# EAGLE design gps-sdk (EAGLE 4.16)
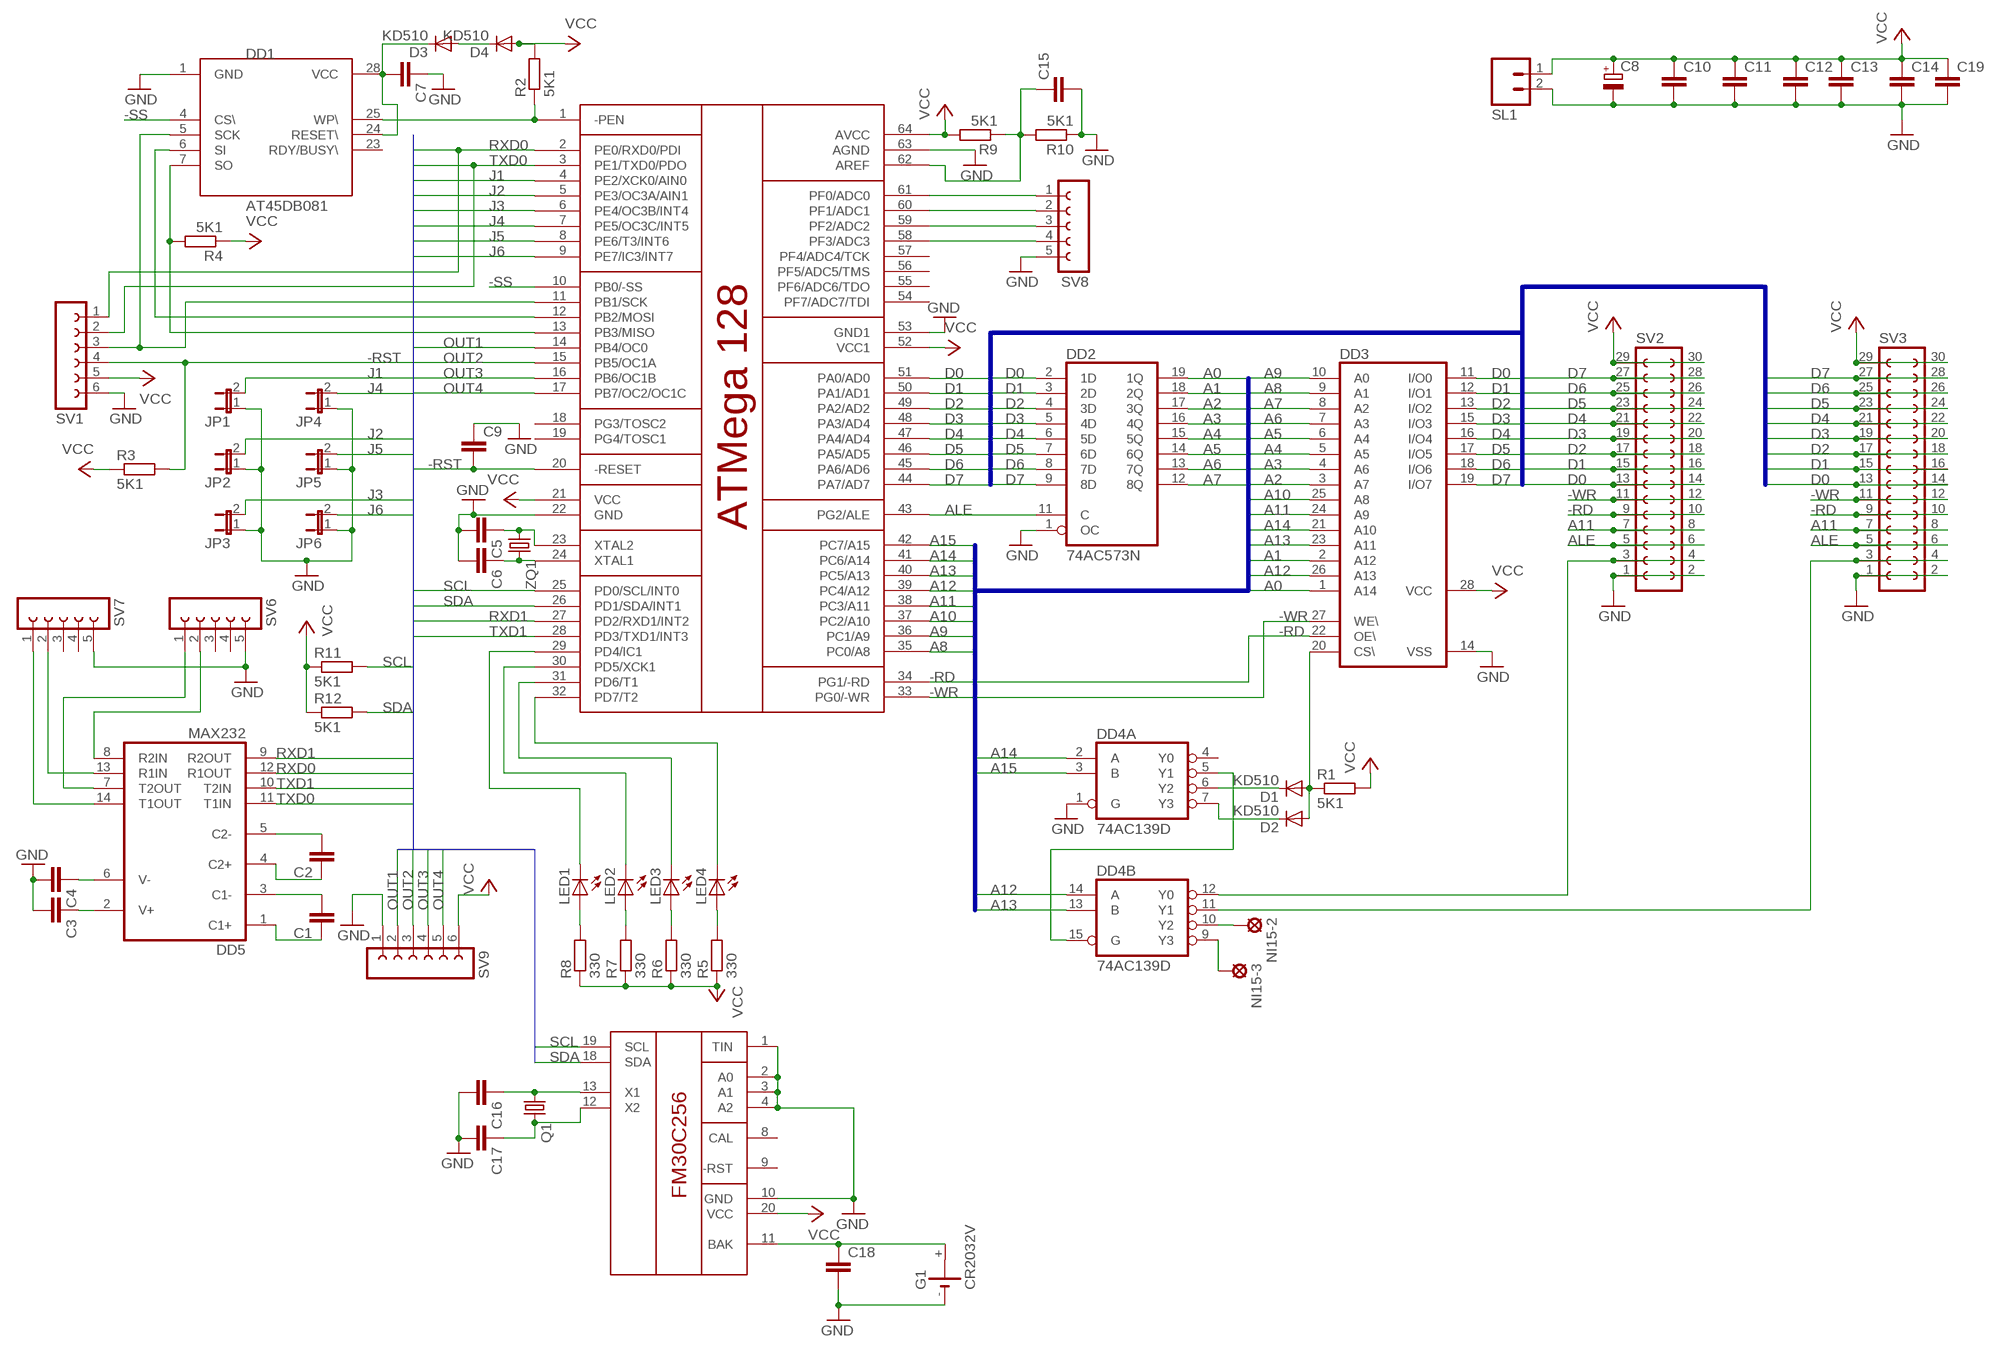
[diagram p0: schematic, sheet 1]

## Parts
C1  C-EUC0805K  [C0805K]
C2  C-EUC0805K  [C0805K]
C3  C-EUC0805K  [C0805K]
C4  C-EUC0805K  [C0805K]
C5  C-EUC0805K  [C0805K]
C6  C-EUC0805K  [C0805K]
C7  C-EUC0805K  [C0805K]
C8  CPOL-EUE5-5  [E5-5]
C9  C-EUC0805K  [C0805K]
C10  C-EUC0805K  [C0805K]
C11  C-EUC0805K  [C0805K]
C12  C-EUC0805K  [C0805K]
C13  C-EUC0805K  [C0805K]
C14  C-EUC0805K  [C0805K]
C15  C-EUC0805K  [C0805K]
C16  C-EUC0805K  [C0805K]
C17  C-EUC0805K  [C0805K]
C18  C-EUC0805K  [C0805K]
C19  C-EUC0805K  [C0805K]
D1  KD510  BAS15  [DO34-7]
D2  KD510  BAS15  [DO34-7]
D3  KD510  BAS15  [DO34-7]
D4  KD510  BAS15  [DO34-7]
DD1  AT45DB081  [AT45DB081-SOIC28]
DD2  74AC573N  [DIL20]
DD3  62256P  [DIL28-6]
DD4  74AC139D  [SO16]
DD5  MAX232  [DIL16]
G1  CR2032V  [CR2032V]
JP1  JP1E  [JP1]
JP2  JP1E  [JP1]
JP3  JP1E  [JP1]
JP4  JP1E  [JP1]
JP5  JP1E  [JP1]
JP6  JP1E  [JP1]
LED1  LEDSMT1206  [1206]
LED2  LEDSMT1206  [1206]
LED3  LEDSMT1206  [1206]
LED4  LEDSMT1206  [1206]
NI15-2  LSP10  [LSP10]
NI15-3  LSP10  [LSP10]
Q1  CRYTALTC26V  [TC26V]
R1  5K1  R-EU_0204/2V  [0204V]
R2  5K1  R-EU_0204/2V  [0204V]
R3  5K1  R-EU_0204/2V  [0204V]
R4  5K1  R-EU_0204/2V  [0204V]
R5  330  R-EU_0204/2V  [0204V]
R6  330  R-EU_0204/2V  [0204V]
R7  330  R-EU_0204/2V  [0204V]
R8  330  R-EU_0204/2V  [0204V]
R9  5K1  R-EU_0204/2V  [0204V]
R10  5K1  R-EU_0204/2V  [0204V]
R11  5K1  R-EU_R1206  [R1206]
R12  5K1  R-EU_R1206  [R1206]
SL1  M02  [02P]
SV1  FE06-1  [FE06]
SV2  FE15-2  [FE15-2]
SV3  FE15-2  [FE15-2]
SV6  FE05-1  [FE05-1]
SV7  FE05-1  [FE05-1]
SV8  FE05-1  [FE05-1]
SV9  FE06-1  [FE06]
U$1  ATMEGA128-TQFP64  [TQFP64]
U$2  FM30C256-SSOP20  [SSOP-20]
ZQ1  CRYTALHC49S  [HC49/S]

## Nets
-RD: DD3.22(OE\) SV2.9 SV2.10 SV3.9 SV3.10 U$1.34(PG1/-RD)
-RST: C9.2 R3.2 SV1.4 U$1.20(-RESET)
-SS: DD1.4(CS\) U$1.10(PB0/-SS)
-WR: DD3.27(WE\) SV2.11 SV2.12 SV3.11 SV3.12 U$1.33(PG0/-WR)
A0: DD2.19(1Q) DD3.1(A14)
A1: DD2.18(2Q) DD3.2(A12)
A2: DD2.17(3Q) DD3.3(A7)
A3: DD2.16(4Q) DD3.4(A6)
A4: DD2.15(5Q) DD3.5(A5)
A5: DD2.14(6Q) DD3.6(A4)
A6: DD2.13(7Q) DD3.7(A3)
A7: DD2.12(8Q) DD3.8(A2)
A8: DD3.9(A1) U$1.35(PC0/A8)
A9: DD3.10(A0) U$1.36(PC1/A9)
A10: DD3.25(A8) U$1.37(PC2/A10)
A11: DD3.24(A9) SV2.7 SV2.8 SV3.7 SV3.8 U$1.38(PC3/A11)
A12: DD3.26(A13) DD4.14(B:A) U$1.39(PC4/A12)
A13: DD3.23(A11) DD4.13(B:B) U$1.40(PC5/A13)
A14: DD3.21(A10) DD4.2(A:A) U$1.41(PC6/A14)
A15: DD4.3(A:B) U$1.42(PC7/A15)
ALE: DD2.11(C) SV2.5 SV2.6 SV3.5 SV3.6 U$1.43(PG2/ALE)
D0: DD2.2(1D) DD3.11(I/O0) SV2.13 SV2.14 SV3.13 SV3.14 U$1.51(PA0/AD0)
D1: DD2.3(2D) DD3.12(I/O1) SV2.15 SV2.16 SV3.15 SV3.16 U$1.50(PA1/AD1)
D2: DD2.4(3D) DD3.13(I/O2) SV2.17 SV2.18 SV3.17 SV3.18 U$1.49(PA2/AD2)
D3: DD2.5(4D) DD3.15(I/O3) SV2.19 SV2.20 SV3.19 SV3.20 U$1.48(PA3/AD4)
D4: DD2.6(5D) DD3.16(I/O4) SV2.21 SV2.22 SV3.21 SV3.22 U$1.47(PA4/AD4)
D5: DD2.7(6D) DD3.17(I/O5) SV2.23 SV2.24 SV3.23 SV3.24 U$1.46(PA5/AD5)
D6: DD2.8(7D) DD3.18(I/O6) SV2.25 SV2.26 SV3.25 SV3.26 U$1.45(PA6/AD6)
D7: DD2.9(8D) DD3.19(I/O7) SV2.27 SV2.28 SV3.27 SV3.28 U$1.44(PA7/AD7)
GND: C3.2 C4.2 C5.2 C6.2 C7.1 C8.- C9.1 C10.2 C11.2 C12.2 C13.2 C14.2 C15.2 C16.2 C17.2 C18.2 C19.2 DD1.1(GND) DD2.1(OC) DD3.14(VSS) DD4.1(A:G) G1.- JP1.1 JP2.1 JP3.1 JP4.1 JP5.1 JP6.1 R10.1 SL1.2 SV1.6 SV2.1 SV2.2 SV3.1 SV3.2 SV6.5 SV7.5 SV8.5 SV9.1 U$1.22(GND) U$1.53(GND1) U$1.63(AGND) U$2.1(TIN) U$2.2(A0) U$2.3(A1) U$2.4(A2) U$2.10(GND)
J1: JP1.2 U$1.4(PE2/XCK0/AIN0)
J2: JP2.2 U$1.5(PE3/OC3A/AIN1)
J3: JP3.2 U$1.6(PE4/OC3B/INT4)
J4: JP4.2 U$1.7(PE5/OC3C/INT5)
J5: JP5.2 U$1.8(PE6/T3/INT6)
J6: JP6.2 U$1.9(PE7/IC3/INT7)
N$1: DD4.12(B:Y0) SV2.3 SV2.4
N$2: DD4.5(A:Y1) DD4.15(B:G)
N$3: D1.C DD4.6(A:Y2)
N$4: D2.C DD4.7(A:Y3)
N$5: D1.A D2.A DD3.20(CS\) R1.1
N$6: DD1.25(WP\) R2.1 U$1.1(-PEN)
N$7: C2.2 DD5.5(C2-)
N$8: C2.1 DD5.4(C2+)
N$9: C1.2 DD5.3(C1-)
N$10: C1.1 DD5.1(C1+)
N$11: C3.1 DD5.2(V+)
N$12: C4.1 DD5.6(V-)
N$13: C6.1 U$1.24(XTAL1) ZQ1.2
N$14: C5.1 U$1.23(XTAL2) ZQ1.1
N$15: DD1.6(SI) U$1.12(PB2/MOSI)
N$16: DD1.7(SO) R4.2 U$1.13(PB3/MISO)
N$17: DD1.5(SCK) SV1.3 U$1.11(PB1/SCK)
N$18: LED2.A R7.2
N$19: D3.A D4.C
N$20: C7.2 D3.C DD1.24(RESET\) DD1.28(VCC)
N$21: DD4.11(B:Y1) SV3.3 SV3.4
N$22: LED4.C U$1.32(PD7/T2)
N$23: LED3.C U$1.31(PD6/T1)
N$24: LED2.C U$1.30(PD5/XCK1)
N$25: LED1.C U$1.29(PD4/IC1)
N$26: LED3.A R6.2
N$27: LED4.A R5.2
N$28: C15.1 R9.1 R10.2 U$1.62(AREF)
N$29: LED1.A R8.2
N$30: DD4.10(B:Y2) NI15-2.MP
N$31: DD4.9(B:Y3) NI15-3.MP
N$32: DD5.14(T1OUT) SV7.1
N$33: DD5.13(R1IN) SV7.2
N$34: DD5.7(T2OUT) SV6.1
N$35: DD5.8(R2IN) SV6.2
N$36: SV8.1 U$1.61(PF0/ADC0)
N$37: SV8.2 U$1.60(PF1/ADC1)
N$38: SV8.3 U$1.59(PF2/ADC2)
N$39: SV8.4 U$1.58(PF3/ADC3)
N$40: C16.1 Q1.1 U$2.13(X1)
N$41: C17.1 Q1.2 U$2.12(X2)
N$42: C18.1 G1.+ U$2.11(BAK)
OUT1: SV9.2 U$1.14(PB4/OC0)
OUT2: SV9.3 U$1.15(PB5/OC1A)
OUT3: SV9.4 U$1.16(PB6/OC1B)
OUT4: SV9.5 U$1.17(PB7/OC2/OC1C)
RXD0: DD5.12(R1OUT) SV1.1 U$1.2(PE0/RXD0/PDI)
RXD1: DD5.9(R2OUT) U$1.27(PD2/RXD1/INT2)
SCL: R11.2 U$1.25(PD0/SCL/INT0) U$2.19(SCL)
SDA: R12.2 U$1.26(PD1/SDA/INT1) U$2.18(SDA)
TXD0: DD5.11(T1IN) SV1.2 U$1.3(PE1/TXD0/PDO)
TXD1: DD5.10(T2IN) U$1.28(PD3/TXD1/INT3)
VCC: C8.+ C10.1 C11.1 C12.1 C13.1 C14.1 C19.1 D4.A DD3.28(VCC) R1.2 R2.2 R3.1 R4.1 R5.1 R6.1 R7.1 R8.1 R9.2 R11.1 R12.1 SL1.1 SV1.5 SV2.29 SV2.30 SV3.29 SV3.30 SV9.6 U$1.21(VCC) U$1.52(VCC1) U$1.64(AVCC) U$2.20(VCC)
Unconnected: DD1.23(RDY/BUSY\) DD4.4(A:Y0) G1.+@1(+) SV6.3 SV6.4 SV7.3 SV7.4 U$1.18(PG3/TOSC2) U$1.19(PG4/TOSC1) U$1.54(PF7/ADC7/TDI) U$1.55(PF6/ADC6/TDO) U$1.56(PF5/ADC5/TMS) U$1.57(PF4/ADC4/TCK) U$2.8(CAL) U$2.9(-RST)

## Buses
D[0..7]
A[0..15]
XP1
B$1

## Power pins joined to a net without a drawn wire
GND: DD2.10(GND) DD4.8(P:GND) DD5.15(GND)
VCC: DD2.20(VCC) DD4.16(P:VCC) DD5.16(VCC)

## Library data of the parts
C1-C7 C9-C19 = rcl:C-EU: CAPACITOR, European symbol
C8 = rcl:CPOL-EU: POLARIZED CAPACITOR, European symbol
D1-D4 = diode:BAS15: DIODE
DD1 = flash:AT45DB081: Package: SOIC32, 32-pin SOIC package, 1,27mm between center of pins
DD2 = 74xx-eu:74*573: 8-bit D latch BUS DRIVER
DD3 = memory-hitachi:62256P: MEMORY
DD4 = 74xx-eu:74*139: Dual 2-line to 4-line DECODER/DEMULTIPLEXER
DD5 = maxim:MAX232: RS232 TRANSEIVER
G1 = battery:CR2032V: LI BATTERY Varta
JP1-JP6 = jumper:JP1E: JUMPER
LED1-LED4 = led:LED: LED
NI15-2 NI15-3 = solpad:LSP10: SOLDER PAD
Q1 ZQ1 = crystal:CRYTAL: CRYSTAL
R1-R12 = rcl:R-EU_: RESISTOR, European symbol
SL1 = con-amp-quick:M02: AMP QUICK CONNECTOR
SV1 SV9 = con-lsta:FE06-1: FEMALE HEADER
SV2 SV3 = con-lsta:FE15-2: FEMALE HEADER
SV6-SV8 = con-lsta:FE05-1: FEMALE HEADER
U$1 = ATMega128:ATMEGA128-TQFP64
U$2 = FM30C256:FM30C256-SSOP20

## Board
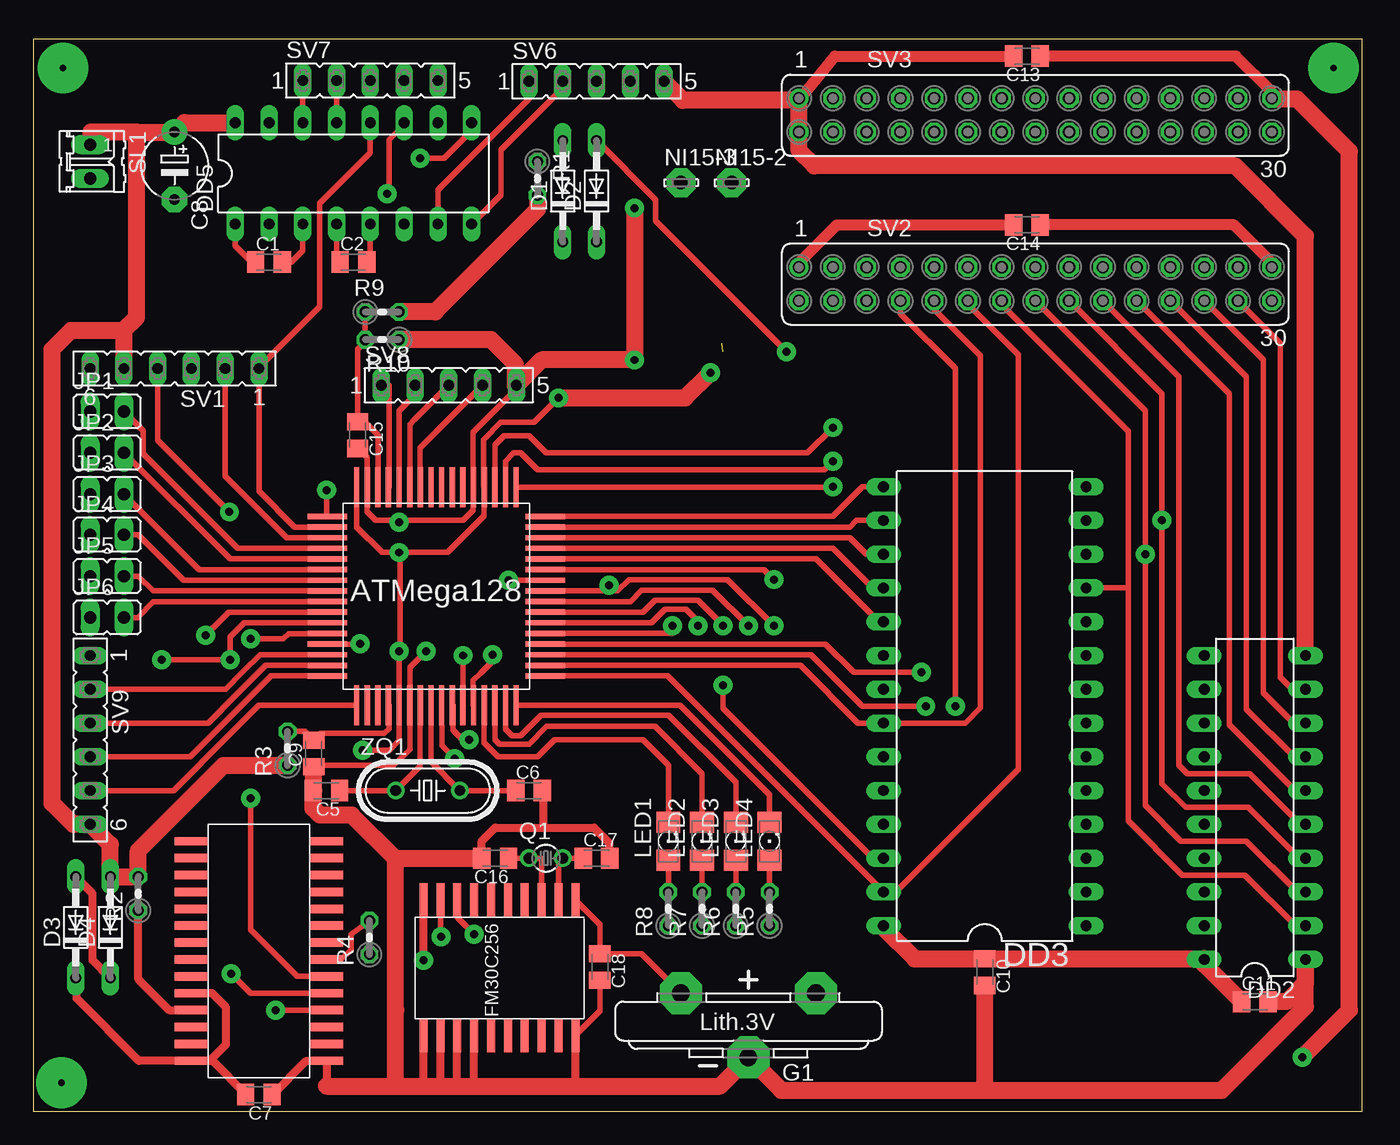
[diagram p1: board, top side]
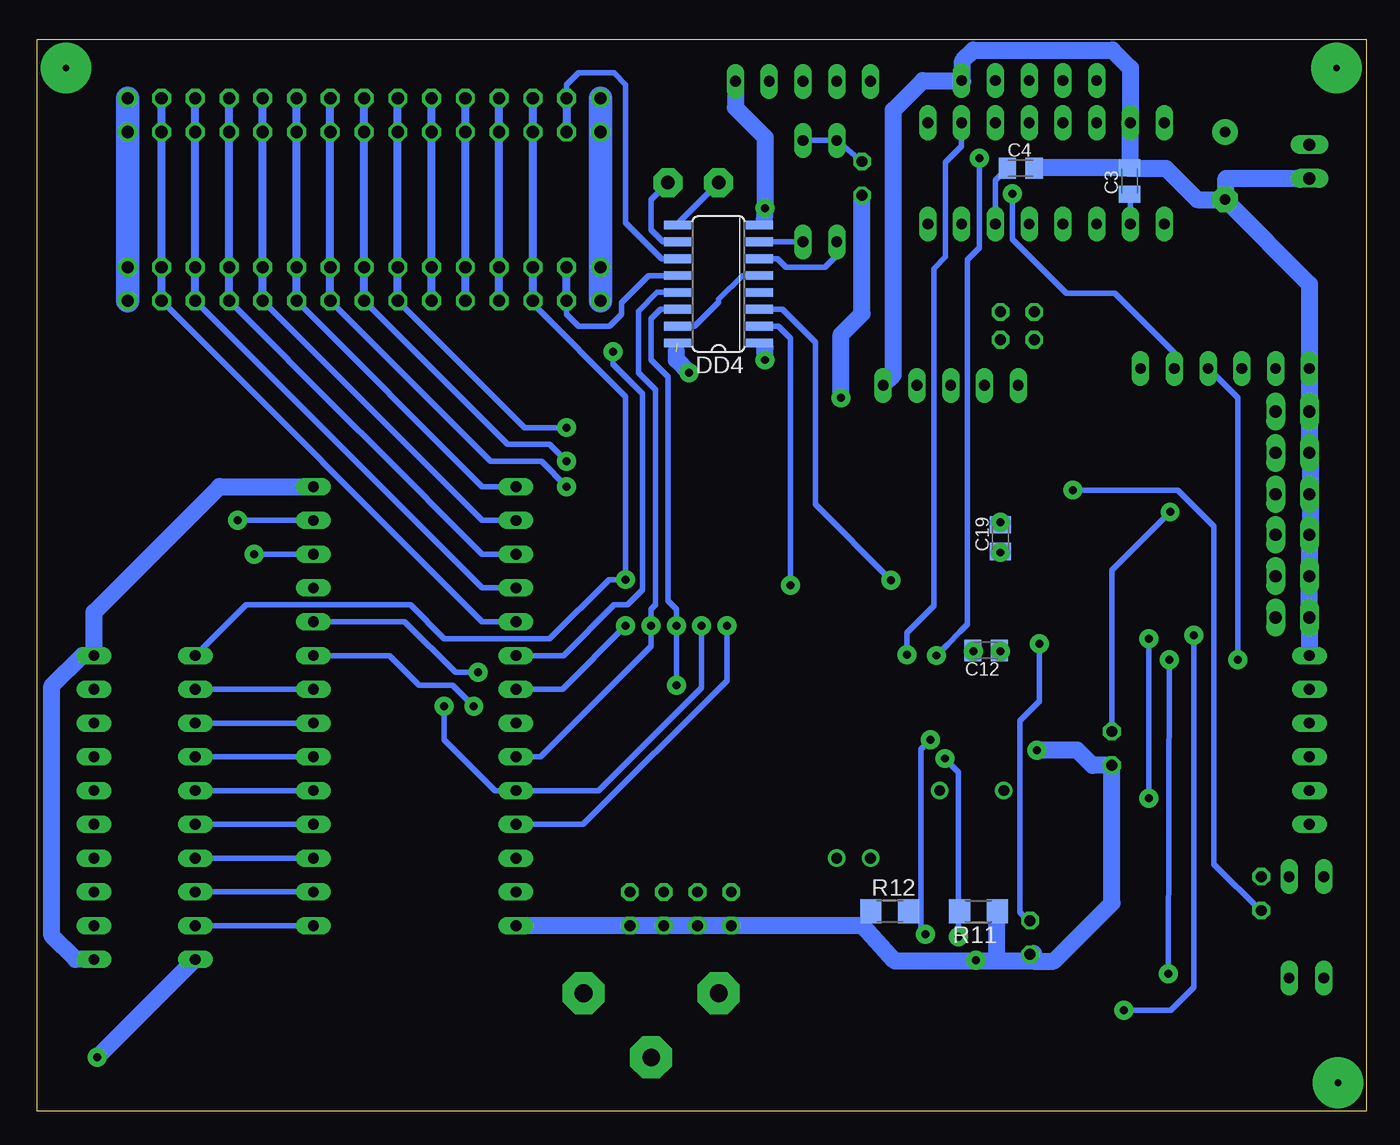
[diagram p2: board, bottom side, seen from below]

Size 100 x 80.64 mm. Coordinates in mm from the lower left corner, seen from the top.
Outline: 0,0 100,0 100,80.64 0,80.64 0,0
Copper layers (1*16): Top 0.035mm / dielectric 1.5mm / Bottom 0.035mm
Design rules "default": minimum track width 10mil, minimum drill 24mil, track to track 8mil, track to pad 8mil, pad to pad 8mil, via to via 8mil, smd to smd 8mil, copper to edge 40mil, drill to drill 8mil, minimum pad ring 10mil, minimum via ring 8mil, stop-mask expansion 4mil, vias tented up to drill 0mil, thermal gap 10mil

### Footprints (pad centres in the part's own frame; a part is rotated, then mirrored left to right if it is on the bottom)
C0805K = smd 1.3 x 1.6: 1 -1,0; 2 1,0
E5-5 = drill 0.813 pad 1.905 round: + -2.54,0 | drill 0.813 pad 1.905 octagon: - 2.54,0
DO34-7 = drill 0.813 long: A 3.81,0; C -3.81,0
AT45DB081-SOIC28 = smd 2.54 x 0.635: 1 -1.27,-1.27; 2 -1.27,-2.54; 3 -1.27,-3.81; 4 -1.27,-5.08; 5 -1.27,-6.35; 6 -1.27,-7.62; 7 -1.27,-8.89; 8 -1.27,-10.16; 9 -1.27,-11.43; 10 -1.27,-12.7; 11 -1.27,-13.97; 12 -1.27,-15.24; 13 -1.27,-16.51; 14 -1.27,-17.78; 15 8.89,-17.78; 16 8.89,-16.51; 17 8.89,-15.24; 18 8.89,-13.97; 19 8.89,-12.7; 20 8.89,-11.43; 21 8.89,-10.16; 22 8.89,-8.89; 23 8.89,-7.62; 24 8.89,-6.35; 25 8.89,-5.08; 26 8.89,-3.81; 27 8.89,-2.54; 28 8.89,-1.27
DIL20 = drill 0.813 long: 1 -11.43,-3.81; 2 -8.89,-3.81; 3 -6.35,-3.81; 4 -3.81,-3.81; 5 -1.27,-3.81; 6 1.27,-3.81; 7 3.81,-3.81; 8 6.35,-3.81; 9 8.89,-3.81; 10 11.43,-3.81; 11 11.43,3.81; 12 8.89,3.81; 13 6.35,3.81; 14 3.81,3.81; 15 1.27,3.81; 16 -1.27,3.81; 17 -3.81,3.81; 18 -6.35,3.81; 19 -8.89,3.81; 20 -11.43,3.81
DIL28-6 = drill 0.813 long: 1 -16.51,-7.62; 2 -13.97,-7.62; 3 -11.43,-7.62; 4 -8.89,-7.62; 5 -6.35,-7.62; 6 -3.81,-7.62; 7 -1.27,-7.62; 8 1.27,-7.62; 9 3.81,-7.62; 10 6.35,-7.62; 11 8.89,-7.62; 12 11.43,-7.62; 13 13.97,-7.62; 14 16.51,-7.62; 15 16.51,7.62; 16 13.97,7.62; 17 11.43,7.62; 18 8.89,7.62; 19 6.35,7.62; 20 3.81,7.62; 21 1.27,7.62; 22 -1.27,7.62; 23 -3.81,7.62; 24 -6.35,7.62; 25 -8.89,7.62; 26 -11.43,7.62; 27 -13.97,7.62; 28 -16.51,7.62
SO16 = smd 0.66 x 2.032: 1 -4.445,-3.073; 2 -3.175,-3.073; 3 -1.905,-3.073; 4 -0.635,-3.073; 5 0.635,-3.073; 6 1.905,-3.073; 7 3.175,-3.073; 8 4.445,-3.073; 9 4.445,3.073; 10 3.175,3.073; 11 1.905,3.073; 12 0.635,3.073; 13 -0.635,3.073; 14 -1.905,3.073; 15 -3.175,3.073; 16 -4.445,3.073
DIL16 = drill 0.813 long: 1 -8.89,-3.81; 2 -6.35,-3.81; 3 -3.81,-3.81; 4 -1.27,-3.81; 5 1.27,-3.81; 6 3.81,-3.81; 7 6.35,-3.81; 8 8.89,-3.81; 9 8.89,3.81; 10 6.35,3.81; 11 3.81,3.81; 12 1.27,3.81; 13 -1.27,3.81; 14 -3.81,3.81; 15 -6.35,3.81; 16 -8.89,3.81
CR2032V = drill 1.321 pad 3.15 octagon: + -2.54,-5.08; +@1 -2.54,5.08; - 2.286,0
JP1 = drill 0.914 long: 1 0,-1.27; 2 0,1.27
1206 = smd 1.6 x 1.803: A -1.422,0; C 1.422,0
LSP10 = drill 1.016 pad 2.159 octagon: MP 0,0
TC26V = drill 0.813 round: 1 -1.27,0; 2 1.27,0
0204V = drill 0.813 octagon: 1 -1.27,0; 2 1.27,0
R1206 = smd 1.6 x 1.803: 1 -1.422,0; 2 1.422,0
02P = drill 0.914 long: 1 -1.27,0; 2 1.27,0
FE06 = drill 0.813 long: 1 -6.35,0; 2 -3.81,0; 3 -1.27,0; 4 1.27,0; 5 3.81,0; 6 6.35,0
FE15-2 = drill 0.914 round: 1 -17.78,1.27 | drill 0.914 octagon: 2 -17.78,-1.27; 3 -15.24,1.27; 4 -15.24,-1.27; 5 -12.7,1.27; 6 -12.7,-1.27; 7 -10.16,1.27; 8 -10.16,-1.27; 9 -7.62,1.27; 10 -7.62,-1.27; 11 -5.08,1.27; 12 -5.08,-1.27; 13 -2.54,1.27; 14 -2.54,-1.27; 15 0,1.27; 16 0,-1.27; 17 2.54,1.27; 18 2.54,-1.27; 19 5.08,1.27; 20 5.08,-1.27; 21 7.62,1.27; 22 7.62,-1.27; 23 10.16,1.27; 24 10.16,-1.27; 25 12.7,1.27; 26 12.7,-1.27; 27 15.24,1.27; 28 15.24,-1.27; 29 17.78,1.27; 30 17.78,-1.27
FE05-1 = drill 0.813 long: 1 -5.08,0; 2 -2.54,0; 3 0,0; 4 2.54,0; 5 5.08,0
TQFP64 = smd 3 x 0.4: 1 -1.2,13; 2 -1.2,12.2; 3 -1.2,11.4; 4 -1.2,10.6; 5 -1.2,9.8; 6 -1.2,9; 7 -1.2,8.2; 8 -1.2,7.4; 9 -1.2,6.6; 10 -1.2,5.8; 11 -1.2,5; 12 -1.2,4.2; 13 -1.2,3.4; 14 -1.2,2.6; 15 -1.2,1.8; 16 -1.2,1; 33 15.2,1; 34 15.2,1.8; 35 15.2,2.6; 36 15.2,3.4; 37 15.2,4.2; 38 15.2,5; 39 15.2,5.8; 40 15.2,6.6; 41 15.2,7.4; 42 15.2,8.2; 43 15.2,9; 44 15.2,9.8; 45 15.2,10.6; 46 15.2,11.4; 47 15.2,12.2; 48 15.2,13 | smd 0.4 x 3: 17 1,-1.2; 18 1.8,-1.2; 19 2.6,-1.2; 20 3.4,-1.2; 21 4.2,-1.2; 22 5,-1.2; 23 5.8,-1.2; 24 6.6,-1.2; 25 7.4,-1.2; 26 8.2,-1.2; 27 9,-1.2; 28 9.8,-1.2; 29 10.6,-1.2; 30 11.4,-1.2; 31 12.2,-1.2; 32 13,-1.2; 49 13,15.2; 50 12.2,15.2; 51 11.4,15.2; 52 10.6,15.2; 53 9.8,15.2; 54 9,15.2; 55 8.2,15.2; 56 7.4,15.2; 57 6.6,15.2; 58 5.8,15.2; 59 5,15.2; 60 4.2,15.2; 61 3.4,15.2; 62 2.6,15.2; 63 1.8,15.2; 64 1,15.2
SSOP-20 = smd 2.54 x 0.6: 1 -1.27,12.7; 2 -1.27,11.43; 3 -1.27,10.16; 4 -1.27,8.89; 5 -1.27,7.62; 6 -1.27,6.35; 7 -1.27,5.08; 8 -1.27,3.81; 9 -1.27,2.54; 10 -1.27,1.27; 11 8.89,1.27; 12 8.89,2.54; 13 8.89,3.81; 14 8.89,5.08; 15 8.89,6.35; 16 8.89,7.62; 17 8.89,8.89; 18 8.89,10.16; 19 8.89,11.43; 20 8.89,12.7
HC49/S = drill 0.813 round: 1 -2.413,0; 2 2.413,0

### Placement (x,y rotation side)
C1  17.74,63.88 0 top
C2  24.09,63.88 0 top
C3  17.81,69.97 90 bottom
C4  26,70.92 0 bottom
C5  22.06,24.12 180 top
C6  37.3,24.12 0 top
C7  16.98,1.26 180 top
C8  10.63,71.11 270 top
C9  21.11,26.92 90 top
C10  71.59,10.47 270 top
C11  91.91,8.25 0 top
C12  28.6,34.67 180 bottom
C13  74.77,79.37 180 top
C14  74.77,66.67 180 top
C15  24.41,50.86 270 top
C16  34.76,19.05 180 top
C17  42.38,19.05 0 top
C18  42.63,10.85 270 top
C19  27.52,43.11 90 bottom
D1  39.84,69.21 90 top
D2  42.38,69.21 90 top
D3  3.2,13.84 90 top
D4  5.8,13.84 90 top
DD1  20.79,2.54 180 top
DD2  91.91,22.86 90 top
DD3  71.59,30.48 90 top
DD4  48.73,62.23 90 bottom
DD5  24.09,70.54 0 top
G1  53.81,6.34 270 top
JP1  5.55,52.64 270 top
JP2  5.55,49.52 270 top
JP3  5.55,46.41 270 top
JP4  5.55,43.37 270 top
JP5  5.55,40.25 270 top
JP6  5.55,37.14 270 top
LED1  47.78,20.32 90 top
LED2  50.32,20.32 90 top
LED3  52.86,20.32 90 top
LED4  55.4,20.32 90 top
NI15-2  52.54,69.84 0 top
NI15-3  48.73,69.84 0 top
Q1  38.57,19.05 0 top
R1  37.94,70.16 270 top
R2  7.9,16.38 90 top
R3  19.14,27.3 90 top
R4  25.3,13.08 90 top
R5  55.4,15.24 90 top
R6  52.86,15.24 90 top
R7  50.32,15.24 90 top
R8  47.78,15.24 90 top
R9  26.25,60.13 0 top
R10  26.25,58.03 180 top
R11  29.17,15.04 180 bottom
R12  35.84,15.04 0 bottom
SL1  4.28,71.43 270 top
SV1  10.63,55.88 180 top
SV2  75.4,62.23 0 top
SV3  75.4,74.92 0 top
SV6  42.38,77.47 0 top
SV7  25.36,77.53 0 top
SV8  31.27,54.61 0 top
SV9  4.28,27.94 270 top
U$1  23.33,31.75 0 top
U$2  42.06,6.98 90 top
ZQ1  29.68,24.12 0 top

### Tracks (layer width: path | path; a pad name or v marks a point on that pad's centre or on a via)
-RD
  Top 0.406: SV2.10 67.78,60.32 71.27,56.83 71.27,30.35 70.13,29.21 DD3.22 62.06,29.21 57.73,33.55 U$1.34
  Bottom 0.61: SV3.9 SV3.10 SV2.9 SV2.10
-RST  (via drill 0.6 pad 1.42)
  Top 0.406: U$1.20 26.76,30.55 26.76,28.79 26.42,28.44 21.63,28.44 C9.2 | C9.2 21.11,27.87 | R3.2 20.46,28.57 C9.2 | SV1.4 9.36,50.48 v14.76,45.08
  Bottom 0.406: v14.76,45.08 19.14,40.7 R3.2
-SS  (via drill 0.6 pad 1.42)
  Top 0.406: U$1.10 14.71,37.55 v12.98,35.81 | 22.19,7.61 DD1.4 v18.25,7.61
  Bottom 0.406: v12.98,35.81 12.98,9.34 14.71,7.61 v18.25,7.61
-WR
  Top 0.406: SV2.12 70.64,60.95 70.64,60.39 74.13,56.9 74.13,25.73 64.9,16.5 DD3.27 47.73,32.74 U$1.33
  Bottom 0.61: SV3.11 SV3.12 SV2.11 SV2.12
A0
  Bottom 0.406: DD3.1 DD2.19
A1
  Bottom 0.406: DD3.2 DD2.18
A2
  Bottom 0.406: DD3.3 DD2.17
A3
  Bottom 0.406: DD3.4 DD2.16
A4
  Bottom 0.406: DD3.5 DD2.15
A5
  Bottom 0.406: DD3.6 DD2.14
A6
  Bottom 0.406: DD3.7 DD2.13
A7
  Bottom 0.406: DD3.8 DD2.12
A8  (via drill 0.6 pad 1.42)
  Top 0.406: U$1.35 58.51,34.34 62.38,30.48 v67.14,30.48
  Bottom 0.406: v67.14,30.48 68.73,32.06 71.27,32.06 73.5,34.29 DD3.9 79.53,34.29
A9  (via drill 0.6 pad 1.42)
  Top 0.406: U$1.36 59.62,35.15 61.75,33.02 v66.83,33.02
  Bottom 0.406: v66.83,33.02 68.53,33.02 72.34,36.83 DD3.10
A10  (via drill 0.6 pad 1.42)
  Top 0.406: U$1.37 48.09,35.95 v48.09,36.51
  Bottom 0.406: DD3.25 58.91,21.59 48.09,32.4 v48.09,36.51
A11  (via drill 0.6 pad 1.42)
  Top 0.406: SV2.8 65.24,60 69.37,55.88 v69.37,30.48 | U$1.38 46.5,36.74 46.82,37.07 47.53,37.78 49.1,37.78 50,36.88 v50,36.51
  Bottom 0.406: DD3.24 63.65,24.12 | DD3.24 65.54,24.12 69.37,27.95 v69.37,30.48 | v50,36.51 50,31.88 57.75,24.12 DD3.24
  Bottom 0.61: SV3.7 SV3.8 SV2.7 SV2.8
A12  (via drill 0.6 pad 1.42)
  Top 0.406: U$1.39 45.87,37.55 46.76,38.44 50.03,38.44 51.91,36.56 v51.91,36.51 | v51.91,32.06 51.91,30.31 63.17,19.05 DD3.26
  Bottom 0.406: v51.91,32.06 v51.91,36.51 51.91,37.78 52.54,38.41 52.54,55.24 53.81,56.51 53.81,59.61 53.1,60.32 DD4.14
A13  (via drill 0.6 pad 1.42)
  Top 0.406: U$1.40 44.92,38.34 45.78,39.2 51.12,39.2 v53.81,36.51
  Bottom 0.406: 51.91,61.59 DD4.13 53.34,61.59 54.76,60.17 54.76,55.56 53.49,54.29 53.49,38.09 53.81,37.78 v53.81,36.51 53.81,34.98 62.12,26.66 DD3.23
A14  (via drill 0.6 pad 1.42)
  Top 0.406: U$1.41 43.33,39.15 | 43.33,39.15 43.97,39.15 44.82,40 52.22,40 v55.71,36.51 | 43.33,39.15 v43.33,39.56
  Bottom 0.406: 45.55,59.05 DD4.2 44.23,59.05 43.33,58.15 v43.33,39.56 | DD3.21 60.48,31.75 v55.71,36.51
A15  (via drill 0.6 pad 1.42)
  Top 0.406: U$1.42 36.03,39.95 v35.78,39.94
  Bottom 0.406: 45.55,60.32 45.24,60.32 | v35.78,39.94 41.43,45.65 41.43,57.84 43.91,60.32 45.55,60.32 | 45.55,60.32 DD4.3
ALE  (via drill 0.6 pad 1.42)
  Top 0.406: U$1.43 54.97,40.74 v55.71,40
  Bottom 0.406: SV2.6 62.7,60.74 55.71,53.75 v55.71,40 56.98,40 61.43,35.55 69.37,35.55 71.91,38.09 84.29,38.09 DD2.11
  Bottom 0.61: SV3.5 SV3.6 SV2.5 SV2.6
D0  (via drill 0.6 pad 1.42)
  Top 0.406: DD2.2 94.98,13.96 91.17,17.78 86.45,17.78 82.39,21.84 82.39,39.37 | 82.39,39.37 82.39,51.15 72.86,60.68 SV2.14 | 82.39,39.37 DD3.11 | U$1.51 34.73,50.13 34.76,50.13 35.42,50.8 37.3,50.8 38.57,49.52 58.25,49.52 v60.16,51.43
  Bottom 0.406: v60.16,51.43 63.34,51.43 SV2.14
  Bottom 0.61: SV3.13 SV3.14 SV2.13 SV2.14
D1  (via drill 0.6 pad 1.42)
  Top 0.406: DD2.3 95.08,16.5 91.28,20.32 86.35,20.32 83.66,23.01 v83.66,41.91 83.66,52.7 SV2.16 | U$1.50 35.52,48.89 36.16,49.52 36.66,49.52 37.94,48.26 59.52,48.26 v60.16,48.89
  Bottom 0.406: v83.66,41.91 DD3.12 | v60.16,48.89 61.43,50.16 64.61,50.16 SV2.16
  Bottom 0.61: SV3.15 SV3.16 SV2.15 SV2.16
D2  (via drill 0.6 pad 1.42)
  Top 0.406: DD2.4 95.24,19.05 91.43,22.86 86.72,22.86 84.92,24.65 v84.92,44.45 84.92,53.97 SV2.18 | U$1.49 60.16,46.95 v60.16,46.98
  Bottom 0.406: v84.92,44.45 DD3.13 | v60.16,46.98 62.06,48.89 65.88,48.89 SV2.18
  Bottom 0.61: SV3.17 SV3.18 SV2.17 SV2.18
D3
  Top 0.406: DD2.5 95.33,21.59 91.53,25.39 86.83,25.39 86.19,26.03 86.19,55.24 SV2.20 | U$1.48 60.16,44.74 62.4,46.98 DD3.15
  Bottom 0.406: DD3.15 66.51,46.98 SV2.20
  Bottom 0.61: SV3.19 SV3.20 SV2.19 SV2.20
D4
  Top 0.406: DD2.6 94.97,24.12 90,29.09 90,53.97 SV2.22 | U$1.47 61.43,43.95 61.93,44.45 DD3.16
  Bottom 0.406: DD3.16 66.51,44.45 SV2.22
  Bottom 0.61: SV3.21 SV3.22 SV2.21 SV2.22
D5
  Top 0.406: DD2.7 94.87,26.66 91.28,30.26 91.28,55.24 SV2.24 | U$1.46 61.43,43.15 62.67,41.91 DD3.17
  Bottom 0.406: DD3.17 66.51,41.91 74.77,50.16 76.67,52.06 SV2.24
  Bottom 0.61: SV3.23 SV3.24 SV2.23 SV2.24
D6
  Top 0.406: DD2.8 94.83,29.21 92.55,31.5 92.55,56.51 SV2.26 | U$1.45 60.16,42.34 63.14,39.37 DD3.18
  Bottom 0.406: DD3.18 66.51,39.37 SV2.26
  Bottom 0.61: SV3.25 SV3.26 SV2.25 SV2.26
D7
  Top 0.406: DD2.9 94.71,31.75 93.81,32.64 93.81,57.78 SV2.28 | U$1.44 58.89,41.55 63.61,36.83 DD3.19
  Bottom 0.406: DD3.19 66.51,36.83 SV2.28
  Bottom 0.61: SV3.27 SV3.28 SV2.27 SV2.28
GND  (via drill 0.6 pad 1.42)
  Top 0.406: 42.63,10.09 C18.2 42.63,7.55 U$2.10 | 21.17,25.92 21.17,25.9 | C9.1 21.17,25.92 | 28.35,30.48 28.35,27.25 27.13,26.03 21.17,26.03 21.17,25.92 | C5.2 21.11,24.12 | 24.47,49.86 24.47,49.91 | 24.47,49.86 C15.2 | 25.11,46.98 25.11,49.21 24.47,49.84 24.47,49.86 | 28.35,30.48 28.35,30.55 U$1.22 | v29.55,34.6 28.35,33.4 28.35,30.48 | 27.52,44.45 32.33,44.45 33.11,45.22 33.11,46.95 | 25.11,46.98 25.11,46.95 U$1.63 | 27.52,44.45 25.76,44.45 25.11,45.1 25.11,46.98 | 27.52,44.45 v27.52,44.32 | 33.11,46.95 U$1.53 | 33.11,46.95 33.11,51.09 36.28,54.27 36.28,54.61
  Top 0.61: 40.79,1.9 U$2.10 | 29.36,1.9 U$2.1 | 30.63,1.9 U$2.2 | 31.9,1.9 U$2.3 | 33.17,1.9 U$2.4 | 22.06,1.9 DD1.1 20.54,3.8 18,1.26 C7.1 | C17.2 43.33,19.05 43.33,20.2 42.2,21.33 38.38,21.33 | 38.38,21.33 34.75,21.33 33.74,20.33 33.74,19.05 C16.2 | C6.2 38.38,24.12 38.38,21.33 | 27.27,7.61 27.39,7.61
  Top 0.813: SV3.1 57.62,76.04 60.31,79.37 C13.2 | SV2.1 57.62,63.83 60.46,66.67 C14.2
  Top 1.27: C11.2 94.3,8.25 95.72,9.67 DD2.1 95.72,7.88 89.42,1.58 71.59,1.58 | DD2.10 95.72,65.83 90.44,71.11 58.77,71.11 57.62,72.26 SV3.2 57.62,76.04 48.88,76.04 SV6.5 | v45.24,67.94 v45.24,56.51 38.25,56.51 SV8.5 36.28,54.61 36.28,56.19 34.44,58.03 R10.1 | 22.06,1.9 27.27,1.9 | 27.27,1.9 29.36,1.9 30.63,1.9 31.9,1.9 33.17,1.9 40.79,1.9 51.65,1.9 G1.- 56.29,1.58 71.59,1.58 | 71.59,1.58 C10.2 | 33.74,19.05 27.27,19.05 27.27,18.98 | 27.27,1.9 27.27,7.61 27.27,18.98 | C5.2 21.04,24.12 21.04,22.8 21.56,22.28 23.96,22.28 27.27,18.98 | 21.11,24.12 C9.1
  Bottom 0.406: C12.2 29.62,34.67 v29.55,34.6 | C19.2 v27.52,44.32 27.52,44.37
  Bottom 0.61: 45.3,66.99 DD4.8 | 45.24,57.46 DD4.1
  Bottom 1.27: DD3.14 86.28,46.98 95.72,37.55 DD2.10 96.61,34.29 98.89,32 98.89,13.22 97.1,11.43 DD2.1 | 45.3,66.99 v45.24,67.94 45.24,73.26 47.46,75.48 SV6.5 | v45.24,56.51 45.24,57.46 | SV8.5 35.59,55.37 35.59,75.31 33.36,77.53 SV7.5 30.44,77.47 30.38,77.47 30.38,79.01 29.57,79.81 19.1,79.81 17.74,78.46 DD5.15 17.74,74.29 17.8,74.29 C3.2 | 10.57,68.58 10.57,68.51 | 10.57,68.51 10.57,68.39 | C8.- 10.57,68.58 | SL1.2 10.57,70.16 10.57,68.58 | C8.- 10.57,68.51 | 10.57,68.51 4.28,62.23 SV1.6 JP1.1 | C8.- 12.73,68.58 15.08,70.92 17.87,70.92 17.82,70.97 C3.2 | C4.2 24.85,70.92 24.61,70.97 C3.2 | JP1.1 4.28,52.45 | JP2.1 4.28,49.4 | JP1.1 JP2.1 | JP2.1 4.22,49.52 4.22,46.41 | 4.22,43.37 4.22,43.3 | 4.22,43.37 JP4.1 JP5.1 4.34,40.25 4.34,37.14 JP6.1 SV9.1 | 4.22,46.41 JP3.1 | 4.22,46.41 4.22,43.37
  Bottom 1.778: SV3.1 SV3.2 SV2.1 SV2.2
J1
  Top 0.406: JP1.2 8.28,51.18 8.28,49.46 15.39,42.35 15.39,42.34 U$1.4
J2
  Top 0.406: U$1.5 14.8,41.55 JP2.2
J3
  Top 0.406: U$1.6 12.49,40.74 JP3.2
J4
  Top 0.406: 11.33,39.95 U$1.7 | 11.33,39.94 11.33,39.95 | JP4.2 7.91,43.37 11.33,39.95
J5
  Top 0.406: U$1.8 9.04,39.15 7.9,40.25 JP5.2
J6
  Top 0.406: U$1.9 9.04,38.34 7.84,37.14 JP6.2
N$1
  Bottom 0.406: DD4.12 54,62.86 56.03,60.83 56.03,59.95 56.93,59.05 59.26,59.05 60.16,59.95 SV2.4
  Bottom 0.61: SV2.4 SV2.3
N$2
  Bottom 0.406: DD4.15 50.53,59.05 48.73,60.85 48.73,61.06 46.93,62.86 DD4.5 45.55,62.86
N$3
  Bottom 0.406: DD4.6 44.28,64.13 43.65,63.49 40.74,63.49 39.84,64.39 D1.C
N$4
  Bottom 0.406: D2.C DD4.7
N$5  (via drill 0.6 pad 1.42)
  Top 0.406: D2.A 46.82,68.58 46.82,66.99 v56.67,57.15
  Bottom 0.406: R1.1 D1.A D2.A | DD3.20 60.41,34.29 56.6,38.09 55.59,38.09 54.45,39.24 54.45,53.97 56.67,56.19 v56.67,57.15
N$6  (via drill 0.6 pad 1.42)
  Top 0.406: U$1.1 22.06,44.74 v22.06,46.73
  Top 0.61: DD1.25 10.23,7.61 7.9,9.94 R2.1
  Bottom 0.406: v22.06,46.73 14.17,46.73 11.46,44.01 11.46,18.6 7.9,15.04 R2.1
N$7
  Top 0.406: 25.36,66.8 DD5.5 25.36,63.88 C2.2
N$8
  Top 0.406: C2.1 22.82,63.88 DD5.4
N$9
  Top 0.406: 20.28,66.8 DD5.3 20.28,64.74 19.42,63.88 C1.2
N$10
  Top 0.406: C1.1 16.42,63.88 15.2,65.1 DD5.1
N$11
  Bottom 0.406: 17.74,66.67 DD5.2 17.74,68.97 C3.1
N$12
  Bottom 0.406: 27.9,66.67 DD5.6 27.9,70.02 C4.1
N$13
  Top 0.406: U$1.24 29.93,26.28 ZQ1.2 C6.1
N$14
  Top 0.406: U$1.23 29.11,30.55 29.11,25.97 ZQ1.1 C5.1
N$15  (via drill 0.6 pad 1.42)
  Top 0.406: DD1.6 19.87,10.16 16.34,13.68 v16.34,23.55 | v16.34,35.55 18.82,35.55 19.2,35.94 U$1.12
  Bottom 0.406: v16.34,23.55 v16.34,35.55
N$16  (via drill 0.6 pad 1.42)
  Top 0.406: DD1.7 23.18,11.43 23.9,12.15 23.9,13.33 R4.2 | U$1.13 24.6,35.15 v24.6,35.17
  Bottom 0.406: v24.6,35.17 24.6,30.86 26.06,29.4 26.06,14.98 25.3,14.22 R4.2
N$17  (via drill 0.6 pad 1.42)
  Top 0.406: v9.68,33.97 11.9,33.95 14.82,33.95 v14.82,33.97 14.82,35.71 15.85,36.74 U$1.11 | v14.88,10.35 16.34,8.88 DD1.5
  Bottom 0.406: v14.88,10.35 v14.82,33.97 | 9.68,33.9 v9.68,33.97 9.68,53.65 SV1.3
N$18
  Top 0.406: LED2.A R7.2
N$19
  Top 0.61: D4.C 4.47,11.36 4.47,16.38 D3.A 3.2,17.59
N$20
  Top 0.61: C7.2 16.03,1.26 13.49,3.8 DD1.28 | D3.C 3.26,10.03 3.26,8.49 7.95,3.8 DD1.28 | DD1.28 13.27,3.8 14.5,5.04 14.5,7.83 13.45,8.88 DD1.24
N$21
  Bottom 0.406: DD4.11 53.02,64.13 55.71,66.82 55.71,77.2 56.61,78.1 59.26,78.1 60.16,77.2 SV3.3
  Bottom 0.61: SV3.3 SV3.4
N$22
  Top 0.406: U$1.32 48.66,30.55 55.4,23.81 LED4.C 55.4,21.59
N$23
  Top 0.406: U$1.31 35.53,28.75 36.03,28.25 36.66,28.25 38.22,29.8 47.81,29.8 52.86,24.76 LED3.C 52.86,21.59
N$24
  Top 0.406: U$1.30 34.73,27.96 35.08,27.62 37.3,27.62 38.63,28.95 46.76,28.95 50.32,25.39 LED2.C
N$25
  Top 0.406: U$1.29 33.93,27.71 34.98,26.66 37.94,26.66 39.2,27.94 45.87,27.94 47.78,26.03 LED1.C 47.78,21.59
N$26
  Top 0.406: LED3.A R6.2
N$27
  Top 0.406: LED4.A R5.2
N$28
  Top 0.406: U$1.62 25.93,50.84 24.96,51.81 24.41,51.81 | 24.41,51.81 C15.1 24.41,57.34 25.04,57.97 25.04,58.03 R10.2 | 24.41,51.81 24.41,51.75 | 24.98,57.91 R10.2 | R9.1 R10.2
N$29
  Top 0.406: LED1.A R8.2
N$30
  Bottom 0.406: DD4.10 52.91,65.4 53.81,66.3 53.81,68.58 NI15-2.MP
N$31
  Bottom 0.406: DD4.9 51.91,66.67 50.63,67.94 NI15-3.MP
N$32
  Top 0.406: DD5.14 SV7.1
N$33
  Top 0.406: SV7.2 DD5.13
N$34
  Top 0.406: DD5.7 30.44,69.32 31.73,70.61 37.3,76.17 SV6.1
N$35
  Top 0.406: 39.84,77.53 SV6.2 39.84,76.95 37.68,74.8 37.67,74.8 35.2,72.33 35.2,68.96 DD5.8
N$36
  Top 0.406: U$1.61 26.76,46.95 26.76,54.61 SV8.1
N$37
  Top 0.406: U$1.60 27.52,52.7 28.73,53.91 SV8.2 28.73,54.67
N$38
  Top 0.406: U$1.59 28.35,46.95 28.35,51.68 28.66,52 SV8.3 31.27,54.67
N$39
  Top 0.406: U$1.58 29.11,46.95 29.11,49.91 30.5,51.3 SV8.4
N$40
  Top 0.406: U$2.13 38.25,19.05 Q1.1 C16.1
N$41
  Top 0.406: U$2.12 39.52,19.05 Q1.2 C17.1
N$42
  Top 0.406: C18.1 42.63,11.81 | C18.1 42.63,14.03 U$2.11 | 48.73,8.82 G1.+ 45.76,11.85 C18.1
N$43  (via drill 0.5 pad 3.81)
  other vias: 2.25,78.48
N$44  (via drill 0.5 pad 3.81)
  other vias: 97.82,78.48
N$45  (via drill 0.5 pad 3.81)
  other vias: 2.12,2.15
OUT1
  Top 0.406: U$1.14 17.07,34.34 15.77,33.05 14.47,31.75 SV9.2 4.28,31.81
OUT2
  Top 0.406: U$1.15 17.49,33.55 15.27,31.32 13.16,29.21 SV9.3 4.28,29.14
OUT3
  Top 0.406: U$1.16 17.9,32.74 13.62,28.46 11.82,26.66 SV9.4
OUT4
  Top 0.406: 4.15,24.12 SV9.5 | U$1.17 16.97,30.55 14.76,28.33 10.55,24.12 4.15,24.12 | 4.15,24.12 4.15,24.19
RXD0
  Top 0.406: U$1.2 19.67,43.95 16.98,46.64 SV1.1 16.92,55.88 | DD5.12 25.36,72.11 24.31,71.05 21.55,68.3 21.55,60.51 16.92,55.88 | 16.92,55.88 16.92,55.81
RXD1  (via drill 0.6 pad 1.42)
  Top 0.406: U$1.27 32.35,30.55 v32.35,34.29 | v29.11,71.69 30.9,71.69 32.98,73.77 DD5.9
  Bottom 0.406: v32.35,34.29 31.52,35.11 30.57,36.06 30,36.63 30,64.07 29.11,64.96 v29.11,71.69
SCL  (via drill 0.6 pad 1.42)
  Top 0.406: U$1.25 30.75,27.49 v31.71,26.54 | 30.63,15.93 U$2.19 30.63,13.14 v30.7,13.14
  Bottom 0.406: v30.7,13.14 30.7,13.01 | v31.71,26.54 30.7,25.52 v30.7,13.14 | R11.2 30.7,15.04 v30.7,13.14
SDA  (via drill 0.6 pad 1.42)
  Top 0.406: U$1.26 31.58,30.55 31.58,28.65 32.3,27.94 v32.79,27.94 | v33.17,13.33 31.9,14.6 U$2.18
  Bottom 0.406: v32.79,27.94 33.49,27.24 33.49,15.04 | 33.49,15.04 33.49,13.65 v33.17,13.33 | 33.49,15.04 R12.2
TXD0  (via drill 0.6 pad 1.42)
  Top 0.406: U$1.3 19.05,43.15 14.44,47.75 SV1.2 | v26.63,69.02 26.76,69.27 26.76,73.08 28.03,74.35 | 28.03,74.35 DD5.11 | 28.03,74.35 28.03,74.42
  Bottom 0.406: SV1.2 14.44,57.06 18.9,61.53 22.57,61.53 26.63,65.58 v26.63,69.02
TXD1  (via drill 0.6 pad 1.42)
  Top 0.406: U$1.28 33.11,30.55 33.11,32.41 33.65,32.95 34.57,33.87 v34.57,34.35
  Bottom 0.406: v34.57,34.35 34.57,36 32.54,38.03 32.54,63.37 31.65,64.26 31.65,71.37 30.44,72.58 DD5.10
VCC  (via drill 0.6 pad 1.42)  (1 unrouted)
  Top 0.406: U$1.21 27.52,27.9 26.8,27.17 v24.79,27.17 | U$1.21 | U$1.21 v27.52,34.6 27.58,34.6 | U$1.52 33.94,46.98 33.87,46.98 33.87,50.52 35.16,51.81 37.68,51.81 v39.52,53.65 | U$1.52 | 27.58,42.03 28.79,42.03 | 28.79,42.03 31.17,42.03 33.94,44.8 U$1.52 | 27.58,34.6 27.58,34.54 | 27.58,34.6 27.58,42.03 | 28.79,42.03 v27.52,42.03 | U$1.64 24.35,46.95 24.35,43.92 26.23,42.03 27.58,42.03
  Top 0.61: v29.36,11.36 U$2.20
  Top 0.813: SV3.29 93.18,76.68 90.49,79.37 C13.1 | C14.1 90.34,66.67 93.18,63.83 SV2.29
  Top 1.27: v39.52,53.65 49.05,53.65 v50.95,55.56 | DD3.28 63.97,13.83 66.33,11.47 C10.1 88.1,11.47 DD2.20 | R3.1 14.33,26.03 7.9,19.6 R2.2 D4.A 5.8,20.06 SV9.6 3.01,21.59 1.42,23.17 1.42,57.31 2.84,58.73 6.81,58.73 | 6.81,58.73 6.82,57.38 SV1.5 | SL1.1 4.34,72.7 4.34,73.66 7.77,73.66 | 7.77,73.66 C8.+ 10.69,73.66 | 10.69,73.66 10.69,73.59 | DD5.16 11.39,74.35 10.69,73.66 | 6.81,58.73 7.77,59.7 7.77,73.66 | SV3.29 93.18,76.13 95.09,76.13 99.02,72.2 99.02,7.61 v95.47,4.06 | DD2.20 88.1,11.49 | DD2.20 88.1,11.06 C11.1 | R1.2 37.94,67.83 30.24,60.13 R9.2
  Bottom 0.406: C12.1 27.58,34.67 v27.52,34.6 | C19.1 v27.52,42.03 | R12.1 37.87,15.04 37.87,13.96
  Bottom 0.61: 30.5,11.3 30.5,11.36 v29.36,11.36
  Bottom 1.27: DD3.28 R5.1 R6.1 R7.1 R8.1 37.87,13.96 35.46,11.3 30.5,11.3 27.77,11.3 | R1.2 37.94,60 39.52,58.41 v39.52,53.65 | v50.95,55.56 51.91,56.51 51.91,57.15 | v24.79,27.17 21.74,27.17 20.6,26.03 R3.1 19.14,15.67 23.51,11.3 25.04,11.3 | 25.04,11.3 27.77,11.3 | R4.1 25.04,11.87 25.04,11.3 | DD2.20 v95.47,4.06 | R11.1 27.77,15.04 27.77,11.3
  Bottom 1.778: SV3.29 SV3.30 SV2.29 SV2.30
